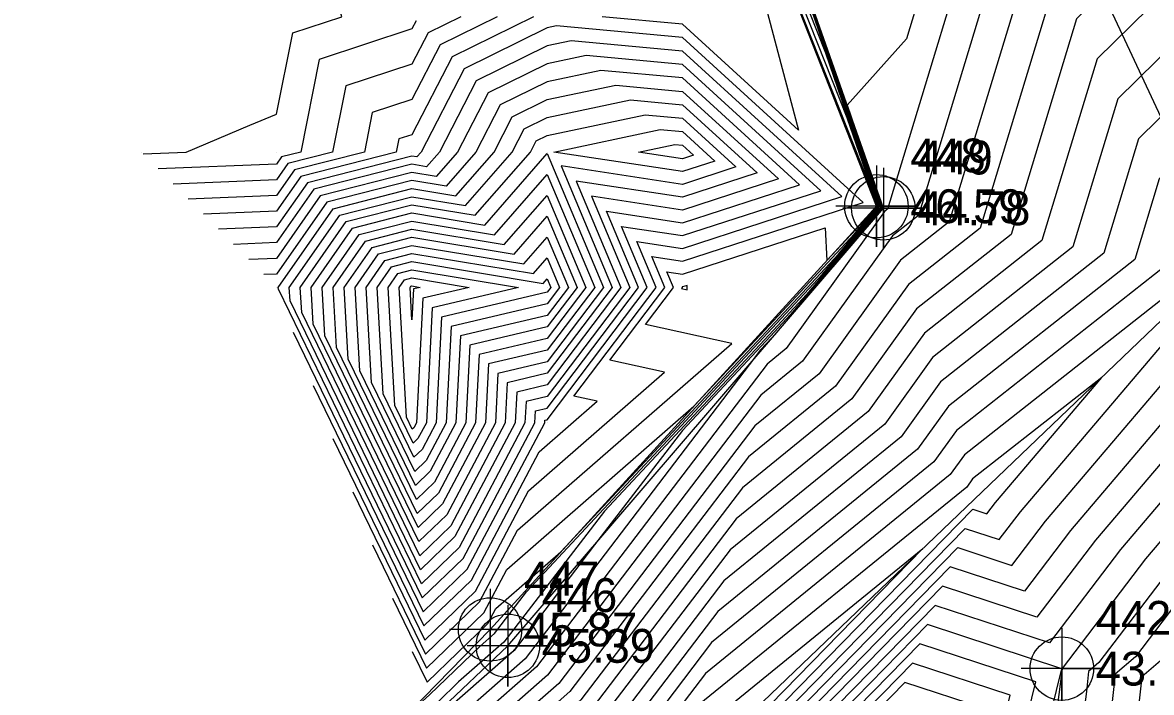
# Model space of a CAD drawing. Extents: x 2090860 to 2091277, y 159470 to 160080.
# Drawn here: x 2090961.2 to 2091044.6, y 159730.1 to 159779.6 of the extents above; entities that cross this region are included whole.
import ezdxf

# ---------------------------------------------------------------- set-up
doc = ezdxf.new("R2010")
doc.units = 0
for name, color, linetype in [('DTM Contours Major', 7, 'Continuous'), ('DTM Contours Minor', 7, 'Continuous'), ('Exist DTM Breakline', 7, 'Continuous'), ('Exist DTM Breakline Cogo Elevation', 7, 'Continuous'), ('Exist DTM Breakline Cogo Number', 7, 'Continuous'), ('Exist DTM Breakline Cogo Point CELL', 7, 'Continuous'), ('Exist DTM Breakline Underwater', 7, 'Continuous'), ('Exist DTM QL2 LIDAR Elevation Point', 7, 'Continuous'), ('Exist DTM Regular Point Underwater CELL', 7, 'Continuous'), ('Exist DTM Regular Point Underwater Cogo Elevation', 7, 'Continuous'), ('Exist DTM Regular Point Underwater Cogo Number', 7, 'Continuous'), ('Exist Structure Major Deck Tunnel Box Culvert', 7, 'Continuous')]:
    doc.layers.add(name, color=color, linetype=linetype)

msp = doc.modelspace()

# ---------------------------------------------------------------- linework, layer by layer
at = {"layer": 'DTM Contours Major'}
for points in [[(2091091.582, 159898.637), (2091075.464, 159895.754), (2091071.361, 159891.649), (2091065.515, 159864.769), (2091059.162, 159855.905), (2091062.527, 159845.344), (2091062.382, 159844.528), (2091071.24, 159827.424), (2091068.468, 159817.052), (2091062.553, 159811.484), (2091060.259, 159801.479), (2091046.876, 159791.945), (2091037.586, 159782.801), (2091031.987, 159764.384), (2091026.688, 159760.214), (2091021.294, 159752.688), (2091014.874, 159747.469), (2091001.671, 159730.125), (2090998.416, 159727.263), (2090990.823, 159719.668), (2090976.25, 159706.989)], [(2091099.517, 159890.851), (2091094.379, 159889.932), (2091085.334, 159880.882), (2091082.516, 159867.927), (2091070.303, 159850.886), (2091072.441, 159844.175), (2091072.201, 159842.82), (2091077.78, 159832.047), (2091073.12, 159814.614), (2091069.924, 159811.606), (2091065.116, 159790.633), (2091059.844, 159786.877), (2091043.696, 159770.983), (2091041.123, 159762.521), (2091029.056, 159753.026), (2091026.145, 159748.964), (2091013.055, 159738.321), (2091004.963, 159727.692), (2091002.968, 159725.938), (2090989.66, 159712.626), (2090981.654, 159705.661)], [(2091031.476, 159794.619), (2091026.533, 159778.36), (2091022.159, 159773.459), (2091024.771, 159765.861), (2091016.801, 159756.497), (2091016.608, 159756.29), (2091015.762, 159755.383), (2091014.915, 159754.282), (2090998.378, 159732.557), (2090993.863, 159728.588), (2090991.986, 159726.71), (2090970.846, 159708.318)], [(2090990.025, 159733.1), (2090991.131, 159730.822), (2090995.615, 159735.148), (2090996.203, 159736.261), (2091001.006, 159740.45), (2091016.166, 159756.714), (2091021.521, 159762.459), (2091024.488, 159765.945), (2091020.583, 159777.303), (2091016.37, 159787.941)], [(2091087.501, 159783.333), (2091087.769, 159779.288), (2091084.366, 159766.629), (2091076.14, 159769.26), (2091074.973, 159768.174), (2091066.061, 159756.411), (2091053.904, 159745.604), (2091047.888, 159738.533), (2091043.463, 159732.701), (2091041.966, 159731.422), (2091041.639, 159728.479), (2091039.685, 159713.437), (2091038.871, 159704.507), (2091038.64, 159701.617), (2091029.076, 159698.576), (2091027.234, 159702.684), (2091029.528, 159709.044), (2091030.086, 159713.086), (2091034.203, 159729.856), (2091026.977, 159732.23), (2091019.254, 159724.332), (2091013.442, 159718.102), (2090999.017, 159707.674), (2090991.506, 159701.21)], [(2091075.953, 159781.891), (2091074.613, 159776.904), (2091071.372, 159777.941), (2091070.912, 159777.513), (2091056.779, 159758.858), (2091051.193, 159753.892), (2091040.5, 159741.323), (2091036.181, 159735.631), (2091029.212, 159737.921), (2091015.739, 159724.142), (2091012.177, 159720.324), (2091003.337, 159713.933), (2090990.035, 159702.486)], [(2090993.61, 159780), (2090991.192, 159778.808), (2090990, 159776.498), (2090985.116, 159774.884), (2090984.142, 159770), (2090980.842, 159769.158), (2090980, 159767.952), (2090972.364, 159767.636)], [(2090984.165, 159748.824), (2090990.886, 159734.977), (2090994.399, 159738.365), (2090999.406, 159747.849), (2091003.692, 159751.587), (2091001.967, 159751.967), (2091008.037, 159760), (2091006.614, 159763.386), (2091010, 159762.874), (2091021.772, 159766.708), (2091010, 159777.464), (2091001.775, 159778.225), (2091000, 159777.85), (2090994.743, 159775.257), (2090992.03, 159770), (2090991.083, 159768.917), (2090990, 159769.096), (2090982.753, 159767.247), (2090980, 159763.304), (2090976.827, 159763.173)], [(2090984.664, 159765.336), (2090990, 159766.697), (2090993.956, 159766.044), (2090997.413, 159770), (2090998.294, 159771.706), (2091000, 159772.548), (2091006.15, 159773.85), (2091010, 159773.494), (2091015.51, 159768.459), (2091010, 159766.664), (2091002.146, 159767.854), (2091005.447, 159760), (2091000, 159752.791), (2090997.742, 159752.258), (2090997.626, 159750), (2090993.182, 159741.583), (2090990.641, 159739.131), (2090980.995, 159759.005), (2090980.939, 159760), (2090984.664, 159765.336)], [(2090986.575, 159763.425), (2090990, 159764.299), (2090996.829, 159763.171), (2091000, 159766.799), (2091002.858, 159760), (2091000, 159756.218), (2090994.969, 159755.031), (2090994.711, 159750), (2090991.966, 159744.8), (2090990.396, 159743.286), (2090984.437, 159755.563), (2090984.184, 159760), (2090986.575, 159763.425)], [(2090988.486, 159761.514), (2090990, 159761.9), (2090999.703, 159760.297), (2091000, 159760.638), (2091000.268, 159760), (2091000, 159759.645), (2090992.197, 159757.803), (2090991.796, 159750), (2090990.749, 159748.018), (2090990.151, 159747.44), (2090987.879, 159752.121), (2090987.429, 159760), (2090988.486, 159761.514)], [(2090988.564, 159703.762), (2091007.657, 159720.192), (2091010.912, 159722.546), (2091012.224, 159723.952), (2091031.448, 159743.611), (2091032.475, 159743.273), (2091033.111, 159744.112), (2091040.966, 159753.345), (2091031.424, 159745.838), (2091030.995, 159745.239), (2091011.235, 159729.174), (2091008.255, 159725.259), (2091007.521, 159724.613), (2090988.497, 159705.583), (2090987.059, 159704.332)]]:
    msp.add_lwpolyline(points, dxfattribs=at)
at = {"layer": 'DTM Contours Minor'}
for points in [[(2091085.63, 159904.476), (2091061.277, 159900.12), (2091060.882, 159899.725), (2091052.763, 159862.4), (2091050.806, 159859.669), (2091055.091, 159846.22), (2091055.018, 159845.809), (2091066.336, 159823.957), (2091064.979, 159818.88), (2091057.025, 159811.393), (2091056.616, 159809.613), (2091037.15, 159795.745), (2091033.004, 159791.665), (2091025.134, 159765.782), (2091024.911, 159765.606), (2091017.656, 159755.482), (2091016.238, 159754.329), (2090999.201, 159731.949), (2090995.001, 159728.257), (2090991.695, 159724.95), (2090972.197, 159707.986)], [(2091087.614, 159902.53), (2091066.006, 159898.665), (2091064.375, 159897.033), (2091057.014, 159863.189), (2091053.591, 159858.414), (2091057.57, 159845.928), (2091057.473, 159845.382), (2091067.971, 159825.113), (2091066.142, 159818.271), (2091058.867, 159811.424), (2091057.831, 159806.902), (2091040.392, 159794.478), (2091034.531, 159788.71), (2091027.419, 159765.316), (2091025.503, 159763.809), (2091018.868, 159754.551), (2091015.783, 159752.042), (2091000.024, 159731.341), (2090996.139, 159727.925), (2090991.404, 159723.189), (2090973.548, 159707.654)], [(2091089.598, 159900.583), (2091070.735, 159897.209), (2091067.868, 159894.341), (2091061.264, 159863.979), (2091056.377, 159857.16), (2091060.048, 159845.636), (2091059.927, 159844.955), (2091069.606, 159826.269), (2091067.305, 159817.661), (2091060.71, 159811.454), (2091059.045, 159804.19), (2091043.634, 159793.212), (2091036.059, 159785.755), (2091029.703, 159764.85), (2091026.095, 159762.012), (2091020.081, 159753.62), (2091015.328, 159749.755), (2091000.847, 159730.733), (2090997.277, 159727.594), (2090991.114, 159721.429), (2090974.899, 159707.322)], [(2091093.566, 159896.69), (2091080.192, 159894.298), (2091074.854, 159888.957), (2091069.765, 159865.558), (2091061.947, 159854.65), (2091065.005, 159845.052), (2091064.837, 159844.101), (2091072.875, 159828.58), (2091069.631, 159816.443), (2091064.396, 159811.515), (2091061.473, 159798.767), (2091050.118, 159790.678), (2091039.113, 159779.846), (2091034.271, 159763.918), (2091027.28, 159758.417), (2091022.507, 159751.757), (2091014.419, 159745.182), (2091002.494, 159729.516), (2090999.554, 159726.932), (2090990.532, 159717.907), (2090977.601, 159706.657)], [(2091095.549, 159894.744), (2091084.921, 159892.843), (2091078.348, 159886.266), (2091074.015, 159866.348), (2091064.733, 159853.396), (2091067.484, 159844.76), (2091067.291, 159843.674), (2091074.51, 159829.736), (2091070.794, 159815.833), (2091066.238, 159811.545), (2091062.688, 159796.056), (2091053.36, 159789.411), (2091040.641, 159776.892), (2091036.555, 159763.452), (2091027.872, 159756.62), (2091023.719, 159750.826), (2091013.964, 159742.895), (2091003.317, 159728.908), (2091000.692, 159726.601), (2090990.241, 159716.147), (2090978.952, 159706.325)], [(2091097.533, 159892.797), (2091089.65, 159891.387), (2091081.841, 159883.574), (2091078.266, 159867.137), (2091067.518, 159852.141), (2091069.963, 159844.468), (2091069.746, 159843.247), (2091076.145, 159830.892), (2091071.957, 159815.224), (2091068.081, 159811.575), (2091063.902, 159793.344), (2091056.602, 159788.144), (2091042.168, 159773.937), (2091038.839, 159762.987), (2091028.464, 159754.823), (2091024.932, 159749.895), (2091013.509, 159740.608), (2091004.14, 159728.3), (2091001.83, 159726.269), (2090989.951, 159714.386), (2090980.303, 159705.993)], [(2091101.501, 159888.904), (2091099.107, 159888.476), (2091088.827, 159878.19), (2091086.766, 159868.717), (2091073.088, 159849.632), (2091074.92, 159843.883), (2091074.655, 159842.393), (2091079.415, 159833.203), (2091074.283, 159814.005), (2091071.767, 159811.636), (2091066.33, 159787.921), (2091063.086, 159785.61), (2091045.223, 159768.028), (2091043.407, 159762.055), (2091029.648, 159751.229), (2091027.357, 159748.032), (2091012.6, 159736.034), (2091005.786, 159727.084), (2091004.106, 159725.607), (2090989.369, 159710.865), (2090983.005, 159705.329)], [(2090970.132, 159769.868), (2090973.322, 159770), (2090978.019, 159771.981), (2090980, 159772.804), (2090981.197, 159778.803), (2090984.819, 159780), (2090982.977, 159787.023), (2090982.607, 159790), (2090980, 159796.374), (2090974.21, 159795.79), (2090970, 159796.878), (2090962.331, 159797.669), (2090961.234, 159797.532), (2090965.339, 159783.984)], [(2090987.095, 159740.962), (2090991.008, 159732.899), (2090995.007, 159736.757), (2090997.804, 159742.055), (2091013.636, 159755.861), (2091007.265, 159757.265), (2091009.332, 159760), (2091008.847, 159761.153), (2091010, 159760.978), (2091020.527, 159764.407), (2091020.664, 159761.989), (2091023.881, 159765.44), (2091024.346, 159765.987), (2091023.734, 159767.768), (2091015.871, 159787.624)], [(2090988.56, 159737.031), (2090991.07, 159731.861), (2090995.311, 159735.952), (2090997.004, 159739.158), (2091010.835, 159751.219), (2091016.055, 159756.82), (2091022.701, 159763.95), (2091024.417, 159765.966), (2091022.158, 159772.536), (2091016.12, 159787.782)], [(2091017.431, 159786.838), (2091024.63, 159765.903), (2091019.161, 159759.478), (2091016.387, 159756.502), (2091004.237, 159743.466), (2090996.79, 159733.786), (2090993.454, 159730.838), (2090991.938, 159729.378), (2090982.952, 159721.358), (2090970.247, 159708.52)], [(2091014.717, 159786.143), (2091018.577, 159771.611), (2091010, 159779.449), (2091004.046, 159780)], [(2091066.328, 159784.343), (2091046.751, 159765.073), (2091045.691, 159761.589), (2091030.24, 159749.432), (2091028.57, 159747.101), (2091012.145, 159733.748), (2091006.609, 159726.476), (2091005.244, 159725.276), (2090989.078, 159709.104), (2090984.356, 159704.996)], [(2091090.414, 159783.295), (2091090.724, 159778.637), (2091086.804, 159764.06), (2091077.332, 159767.09), (2091075.988, 159765.839), (2091068.382, 159755.8), (2091054.582, 159743.532), (2091049.736, 159737.835), (2091046.17, 159733.137), (2091043.929, 159731.221), (2091043.438, 159726.812), (2091041.995, 159715.704), (2091040.889, 159703.567), (2091040.574, 159699.638), (2091027.576, 159695.505), (2091025.072, 159701.089), (2091028.191, 159709.733), (2091028.948, 159715.227), (2091032.299, 159728.875), (2091026.418, 159730.808), (2091020.133, 159724.38), (2091013.758, 159717.546), (2090997.937, 159706.109), (2090991.874, 159700.892)], [(2091019.078, 159782.234), (2091024.701, 159765.882), (2091017.981, 159757.987), (2091016.497, 159756.396), (2091010, 159749.425), (2091003.491, 159740.964), (2090997.555, 159733.165), (2090992.725, 159728.919), (2090992.277, 159728.471), (2090986.347, 159723.312), (2090976.167, 159714.226), (2090970.443, 159708.442)], [(2090989.3, 159703.124), (2091005.497, 159717.062), (2091011.545, 159721.435), (2091013.982, 159724.047), (2091030.33, 159740.766), (2091034.328, 159739.452), (2091036.806, 159742.718), (2091049.838, 159758.036), (2091052.138, 159760.081), (2091068.882, 159782.182)], [(2090987.359, 159726.086), (2090989.738, 159728.489), (2090991.312, 159729.894), (2090995.036, 159733.482), (2090996.1, 159734.422), (2090998.474, 159737.508), (2091016.276, 159756.608), (2091020.341, 159760.969), (2091024.559, 159765.924), (2091019.007, 159782.07)], [(2091078.907, 159781.24), (2091077.051, 159774.335), (2091072.564, 159775.771), (2091071.927, 159775.178), (2091059.099, 159758.246), (2091051.871, 159751.82), (2091042.347, 159740.625), (2091037.107, 159733.72), (2091028.653, 159736.498), (2091016.618, 159724.19), (2091012.493, 159719.768), (2091002.257, 159712.368), (2090990.403, 159702.167)], [(2091081.861, 159780.589), (2091079.489, 159771.767), (2091073.756, 159773.601), (2091072.942, 159772.843), (2091061.42, 159757.634), (2091052.549, 159749.748), (2091044.194, 159739.928), (2091038.048, 159731.828), (2091038.042, 159731.823), (2091038.04, 159731.812), (2091035.064, 159708.902), (2091034.835, 159706.388), (2091034.77, 159705.574), (2091032.077, 159704.717), (2091031.558, 159705.874), (2091032.204, 159707.665), (2091032.361, 159708.804), (2091038.011, 159731.817), (2091028.095, 159735.075), (2091017.497, 159724.237), (2091012.809, 159719.213), (2091001.177, 159710.803), (2090990.771, 159701.848)], [(2090990.305, 159779.695), (2090990, 159779.105), (2090983.157, 159776.843), (2090981.791, 159770), (2090980.364, 159769.636), (2090980, 159769.114), (2090971.248, 159768.752)], [(2090996.298, 159780), (2090992.08, 159777.92), (2090990, 159773.89), (2090987.076, 159772.924), (2090986.493, 159770), (2090981.32, 159768.68), (2090980, 159766.79), (2090973.48, 159766.52)], [(2090998.985, 159780), (2090992.968, 159777.032), (2090990, 159771.283), (2090989.036, 159770.964), (2090988.843, 159770), (2090981.797, 159768.203), (2090980, 159765.628), (2090974.596, 159765.404)], [(2091069.897, 159779.847), (2091054.458, 159759.469), (2091050.515, 159755.964), (2091038.653, 159742.02), (2091035.254, 159737.542), (2091029.771, 159739.343), (2091014.861, 159724.095), (2091011.861, 159720.879), (2091004.417, 159715.498), (2090989.667, 159702.805)], [(2091084.815, 159779.939), (2091081.928, 159769.198), (2091074.948, 159771.43), (2091073.958, 159770.509), (2091063.74, 159757.023), (2091053.226, 159747.676), (2091046.041, 159739.23), (2091040.755, 159732.265), (2091040.004, 159731.622), (2091039.84, 159730.145), (2091037.374, 159711.17), (2091036.853, 159705.448), (2091036.705, 159703.595), (2091030.576, 159701.647), (2091029.396, 159704.279), (2091030.866, 159708.355), (2091031.224, 159710.945), (2091036.107, 159730.837), (2091027.536, 159733.653), (2091018.376, 159724.285), (2091013.126, 159718.657), (2091000.097, 159709.239), (2090991.138, 159701.529)], [(2090985.63, 159744.893), (2090990.947, 159733.938), (2090994.703, 159737.561), (2090998.605, 159744.952), (2091008.664, 159753.724), (2091004.616, 159754.616), (2091008.684, 159760), (2091007.73, 159762.27), (2091010, 159761.926), (2091023.337, 159766.27), (2091010, 159778.456), (2091000.681, 159779.319), (2091000, 159779.175), (2090993.855, 159776.145), (2090990.684, 159770), (2090990.365, 159769.635), (2090990, 159769.695), (2090982.275, 159767.725), (2090980, 159764.466), (2090975.711, 159764.289)], [(2090982.7, 159752.755), (2090990.825, 159736.015), (2090994.095, 159739.17), (2090999.812, 159750), (2090999.821, 159750.179), (2091000, 159750.221), (2091007.389, 159760), (2091005.497, 159764.503), (2091010, 159763.821), (2091020.206, 159767.145), (2091010, 159776.471), (2091002.868, 159777.132), (2091000, 159776.524), (2090995.631, 159774.369), (2090993.376, 159770), (2090991.801, 159768.199), (2090990, 159768.496), (2090983.231, 159766.769), (2090980, 159762.142), (2090977.943, 159762.057)], [(2090981.235, 159756.685), (2090990.763, 159737.054), (2090993.791, 159739.974), (2090999.084, 159750), (2090999.128, 159750.872), (2091000, 159751.077), (2091006.742, 159760), (2091004.38, 159765.62), (2091010, 159764.769), (2091018.641, 159767.583), (2091010, 159775.479), (2091003.962, 159776.038), (2091000, 159775.199), (2090996.518, 159773.482), (2090994.721, 159770), (2090992.52, 159767.48), (2090990, 159767.896), (2090983.708, 159766.292), (2090980, 159760.98), (2090979.059, 159760.941)], [(2090984.186, 159765.814), (2090990, 159767.297), (2090993.238, 159766.762), (2090996.067, 159770), (2090997.406, 159772.594), (2091000, 159773.873), (2091005.056, 159774.944), (2091010, 159774.486), (2091017.076, 159768.021), (2091010, 159765.716), (2091003.263, 159766.737), (2091006.095, 159760), (2091000, 159751.934), (2090998.435, 159751.565), (2090998.355, 159750), (2090993.486, 159740.778), (2090990.702, 159738.092), (2090980.135, 159759.865), (2090980.127, 159760), (2090984.186, 159765.814)], [(2090985.142, 159764.858), (2090990, 159766.098), (2090994.675, 159765.325), (2090998.759, 159770), (2090999.182, 159770.818), (2091000, 159771.222), (2091007.243, 159772.757), (2091010, 159772.501), (2091013.945, 159768.897), (2091010, 159767.612), (2091001.03, 159768.97), (2091004.8, 159760), (2091000, 159753.648), (2090997.049, 159752.951), (2090996.897, 159750), (2090992.878, 159742.387), (2090990.58, 159740.17), (2090981.856, 159758.144), (2090981.75, 159760), (2090985.142, 159764.858)], [(2090988.932, 159703.443), (2091006.577, 159718.627), (2091011.229, 159721.99), (2091013.103, 159723.999), (2091030.889, 159742.188), (2091033.401, 159741.363), (2091034.959, 159743.415), (2091049.16, 159760.108), (2091049.817, 159760.692), (2091058.581, 159772.26), (2091048.278, 159762.119), (2091047.975, 159761.123), (2091030.832, 159747.635), (2091029.783, 159746.17), (2091011.69, 159731.461), (2091007.432, 159725.867), (2091006.383, 159724.945), (2090988.787, 159707.344), (2090985.707, 159704.664)], [(2091010, 159768.559), (2091000.488, 159770), (2091008.337, 159771.663), (2091010, 159771.509), (2091012.38, 159769.334), (2091010, 159768.559)], [(2091010, 159769.507), (2091006.744, 159770), (2091009.431, 159770.569), (2091010, 159770.516), (2091010.815, 159769.772), (2091010, 159769.507)], [(2090985.619, 159764.381), (2090990, 159765.498), (2090995.393, 159764.607), (2091000, 159769.88), (2091004.152, 159760), (2091000, 159754.505), (2090996.356, 159753.644), (2090996.168, 159750), (2090992.574, 159743.192), (2090990.518, 159741.208), (2090982.716, 159757.284), (2090982.561, 159760), (2090985.619, 159764.381)], [(2090986.097, 159763.903), (2090990, 159764.898), (2090996.111, 159763.889), (2091000, 159768.339), (2091003.505, 159760), (2091000, 159755.361), (2090995.662, 159754.338), (2090995.44, 159750), (2090992.27, 159743.996), (2090990.457, 159742.247), (2090983.577, 159756.423), (2090983.372, 159760), (2090986.097, 159763.903)], [(2090987.053, 159762.947), (2090990, 159763.699), (2090997.548, 159762.452), (2091000, 159765.259), (2091002.21, 159760), (2091000, 159757.075), (2090994.276, 159755.724), (2090993.982, 159750), (2090991.662, 159745.605), (2090990.335, 159744.324), (2090985.298, 159754.702), (2090984.995, 159760), (2090987.053, 159762.947)], [(2090987.531, 159762.469), (2090990, 159763.099), (2090998.266, 159761.734), (2091000, 159763.718), (2091001.563, 159760), (2091000, 159757.932), (2090993.583, 159756.417), (2090993.253, 159750), (2090991.358, 159746.409), (2090990.273, 159745.363), (2090986.158, 159753.842), (2090985.806, 159760), (2090987.531, 159762.469)], [(2090988.008, 159761.992), (2090990, 159762.5), (2090998.984, 159761.016), (2091000, 159762.178), (2091000.915, 159760), (2091000, 159758.789), (2090992.89, 159757.11), (2090992.525, 159750), (2090991.054, 159747.213), (2090990.212, 159746.402), (2090987.019, 159752.981), (2090986.618, 159760), (2090988.008, 159761.992)], [(2090988.964, 159761.036), (2090990, 159761.3), (2090997.873, 159760), (2090991.503, 159758.497), (2090991.067, 159750), (2090990.445, 159748.822), (2090990.09, 159748.479), (2090988.74, 159751.26), (2090988.24, 159760), (2090988.964, 159761.036)], [(2090989.442, 159760.558), (2090990, 159760.701), (2090994.243, 159760), (2090990.81, 159759.19), (2090990.338, 159750), (2090990.141, 159749.626), (2090990.028, 159749.518), (2090989.6, 159750.4), (2090989.052, 159760), (2090989.442, 159760.558)], [(2090989.919, 159760.081), (2090990, 159760.101), (2090990.613, 159760), (2090990.117, 159759.883), (2090990, 159757.604), (2090989.863, 159760), (2090989.919, 159760.081)], [(2091010.348, 159759.818), (2091010.33, 159760.138), (2091010, 159760.031), (2091009.964, 159760.036), (2091009.979, 159760), (2091009.914, 159759.914), (2091010.348, 159759.818)], [(2090990.11, 159705.727), (2091008.659, 159724.282), (2091009.079, 159724.651), (2091010.781, 159726.887), (2091027.762, 159740.693), (2091011.346, 159723.904), (2091010.596, 159723.101), (2091008.736, 159721.757), (2090990.11, 159705.727)]]:
    msp.add_lwpolyline(points, dxfattribs=at)
at = {"layer": 'Exist DTM Breakline'}
for points in [[(2090970.238, 159708.524), (2090995.777, 159734.72), (2091024.32, 159765.995), (2091015.838, 159787.603), (2090997.039, 159829.071)], [(2090970.603, 159708.378), (2090997.094, 159733.506), (2091024.833, 159765.843), (2091016.946, 159788.306), (2090998.355, 159829.241)]]:
    msp.add_lwpolyline(points, dxfattribs=at)
at = {"layer": 'Exist DTM Breakline Cogo Point CELL'}
for points in [[(2091024.32, 159768.995), (2091024.32, 159762.995), (2091024.32, 159765.995), (2091027.32, 159765.995), (2091021.32, 159765.995)], [(2091024.833, 159768.843), (2091024.833, 159762.843), (2091024.833, 159765.843), (2091027.833, 159765.843), (2091021.833, 159765.843)], [(2090995.777, 159737.72), (2090995.777, 159731.72), (2090995.777, 159734.72), (2090998.777, 159734.72), (2090992.777, 159734.72)], [(2090997.094, 159736.506), (2090997.094, 159730.506), (2090997.094, 159733.506), (2091000.094, 159733.506), (2090994.094, 159733.506)]]:
    msp.add_lwpolyline(points, dxfattribs=at)
for centre in [(2091024.32, 159765.995), (2091024.833, 159765.843), (2090995.777, 159734.72), (2090997.094, 159733.506)]:
    msp.add_circle(centre, 2.344, dxfattribs=at)
at = {"layer": 'Exist DTM Breakline Underwater'}
msp.add_lwpolyline([(2090988.242, 159704.041), (2091010.175, 159723.841), (2091048.889, 159760.937), (2091068.273, 159783.583), (2091089.722, 159842.139), (2091103.231, 159887.207)], dxfattribs=at)
at = {"layer": 'Exist DTM QL2 LIDAR Elevation Point'}
for p, q in [((2090970, 159770), (2090970, 159770)), ((2090980, 159770), (2090980, 159770)), ((2090990, 159770), (2090990, 159770)), ((2091000, 159770), (2091000, 159770)), ((2091010, 159770), (2091010, 159770)), ((2090980, 159760), (2090980, 159760)), ((2090990, 159760), (2090990, 159760)), ((2091000, 159760), (2091000, 159760)), ((2091010, 159760), (2091010, 159760)), ((2090990, 159750), (2090990, 159750)), ((2091000, 159750), (2091000, 159750))]:
    msp.add_line(p, q, dxfattribs=at)
at = {"layer": 'Exist DTM Regular Point Underwater CELL'}
msp.add_lwpolyline([(2091038.026, 159734.825), (2091038.026, 159728.825), (2091038.026, 159731.825), (2091041.026, 159731.825), (2091035.026, 159731.825)], dxfattribs=at)
msp.add_circle((2091038.026, 159731.825), 2.344, dxfattribs=at)
at = {"layer": 'Exist Structure Major Deck Tunnel Box Culvert'}
msp.add_lwpolyline([(2091083.939, 159746.358), (2091062.342, 159736.259), (2091031.248, 159802.748), (2091052.743, 159813.103)], close=True, dxfattribs=at)

# ---------------------------------------------------------------- texts
at = {"layer": 'Exist DTM Breakline Cogo Elevation'}
for s, p in [('46.59', (2091026.82, 159764.745)), ('44.78', (2091027.333, 159764.593)), ('45.87', (2090998.277, 159733.47)), ('45.39', (2090999.594, 159732.256))]:
    msp.add_text(s, height=2.5, dxfattribs=at).set_placement(p)
at = {"layer": 'Exist DTM Breakline Cogo Number'}
for s, p in [('448', (2091026.82, 159768.495)), ('449', (2091027.333, 159768.343)), ('447', (2090998.277, 159737.22)), ('446', (2090999.594, 159736.006))]:
    msp.add_text(s, height=2.5, dxfattribs=at).set_placement(p)
at = {"layer": 'Exist DTM Regular Point Underwater Cogo Elevation'}
msp.add_text('43.50', height=2.5, dxfattribs=at).set_placement((2091040.526, 159730.575))
at = {"layer": 'Exist DTM Regular Point Underwater Cogo Number'}
msp.add_text('442', height=2.5, dxfattribs=at).set_placement((2091040.526, 159734.325))

doc.saveas('drawing.dxf')
